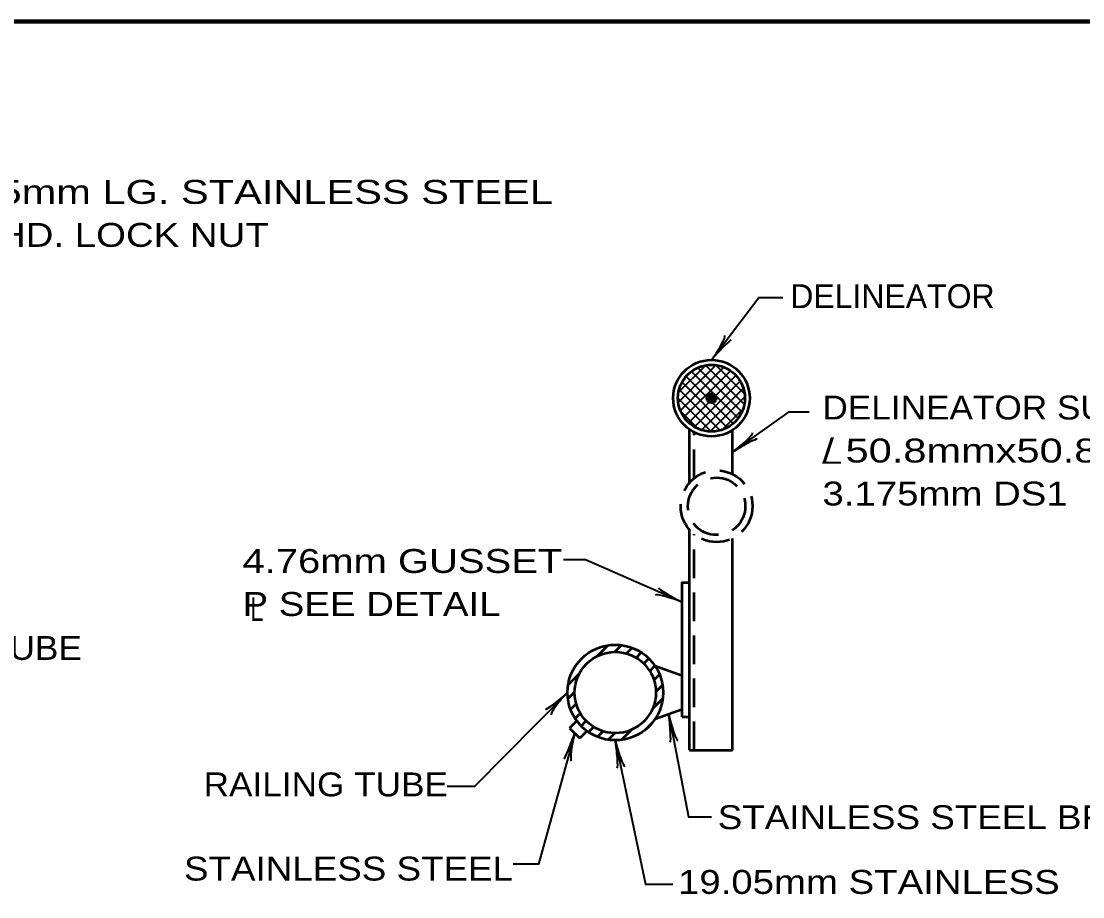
# Model space of a CAD drawing. Extents: x -105 to 751, y -65 to 479.
# Drawn here: x 308.2 to 441.4, y 362.8 to 472.7 of the extents above; entities that cross this region are included whole.
import ezdxf

# ---------------------------------------------------------------- set-up
doc = ezdxf.new("R2010")
doc.units = 0
doc.header["$LTSCALE"] = 1.2
doc.linetypes.add('MEDIUM_DASHED', pattern=[4.5, 3, -1.5])
doc.layers.add('1', color=7, linetype='Continuous', lineweight=35)

msp = doc.modelspace()

# ---------------------------------------------------------------- hatches: boundary and pattern name
at = {"layer": '1'}
msp.add_hatch(color=256, dxfattribs=at).paths.add_polyline_path([(395.414, 425.376, 1), (394.214, 425.376, 1)])

# ---------------------------------------------------------------- linework, layer by layer
for p, q in [((390.651, 424.82), (395.369, 429.538)), ((390.691, 426.134), (394.056, 429.498)), ((390.918, 423.815), (396.375, 429.272)), ((398.641, 423.662), (393.099, 429.203)), ((398.939, 424.636), (394.074, 429.502)), ((398.981, 425.867), (395.305, 429.543)), ((391.367, 422.991), (397.199, 428.823)), ((397.553, 422.204), (391.642, 428.115)), ((391.956, 422.307), (397.882, 428.233)), ((398.172, 422.858), (392.296, 428.734)), ((397.839, 428.282), (397.719, 428.402)), ((395.894, 421.318), (390.755, 426.456)), ((396.801, 421.683), (391.121, 427.364)), ((392.682, 421.76), (398.429, 427.508)), ((393.567, 421.373), (398.816, 426.622)), ((394.759, 421.18), (390.617, 425.322)), ((394.654, 421.186), (399.003, 425.536)), ((393.135, 421.531), (390.967, 423.699)), ((396.14, 421.4), (398.789, 424.049)), ((408.763, 417.317), (411.028, 417.317))]:
    msp.add_line(p, q, dxfattribs=at)
at = {"layer": '1', "lineweight": 53}
for p, q in [((392.049, 414.74), (392.049, 421.452)), ((397.449, 415.837), (397.449, 421.364)), ((392.049, 381.186), (392.049, 408.863)), ((397.449, 381.186), (397.449, 407.767)), ((380.414, 392.949), (381.798, 394.333)), ((382.669, 393.507), (383.52, 394.358)), ((384.166, 393.306), (384.876, 394.017)), ((385.349, 392.793), (386.007, 393.451)), ((386.311, 392.058), (386.946, 392.693)), ((387.071, 391.12), (387.716, 391.766)), ((387.751, 391.752), (391.149, 390.552)), ((376.837, 389.371), (378.236, 390.771)), ((387.603, 389.955), (388.311, 390.664)), ((387.843, 388.499), (388.672, 389.327)), ((376.805, 387.643), (377.657, 388.495)), ((387.408, 386.366), (388.687, 387.646)), ((377.15, 386.29), (377.854, 386.994)), ((391.149, 386.286), (387.751, 385.086)), ((377.721, 385.165), (378.372, 385.816)), ((391.149, 385.386), (392.049, 385.386)), ((377.87, 384.813), (377.021, 383.964)), ((377.021, 383.964), (378.294, 382.692)), ((378.469, 384.216), (379.113, 384.86)), ((379.403, 383.453), (380.052, 384.102)), ((383.52, 382.478), (384.807, 383.765)), ((386.453, 383.715), (387.456, 384.717)), ((379.142, 383.54), (378.294, 382.692)), ((380.509, 382.862), (381.209, 383.562)), ((381.835, 382.491), (382.673, 383.328)), ((392.049, 381.186), (397.449, 381.186))]:
    msp.add_line(p, q, dxfattribs=at)
at = {"layer": '1', "linetype": 'MEDIUM_DASHED', "lineweight": 53}
for p, q in [((392.649, 415.318), (392.649, 421.092)), ((392.649, 381.186), (392.649, 408.285))]:
    msp.add_line(p, q, dxfattribs=at)
at = {"layer": '1', "lineweight": 158}
msp.add_lwpolyline([(744.128, 472.7), (-47.572, 472.6), (-47.472, -53.4)], dxfattribs=at)
at = {"layer": '1'}
for points in [[(394.814, 430.176), (400.753, 437.999), (403.781, 437.999)], [(397.449, 418.6), (404.571, 423.643), (407.073, 423.643)], [(391.149, 399.745), (379.029, 405.073), (376.264, 405.073)], [(376.749, 388.419), (365.073, 376.626), (361.65, 376.626)], [(389.45, 385.686), (391.932, 372.806), (394.829, 372.806)], [(377.657, 383.328), (373.105, 366.88), (369.945, 366.88)], [(382.749, 382.419), (386.534, 364.377), (389.957, 364.377)]]:
    msp.add_lwpolyline(points, dxfattribs=at)
at = {"layer": '1', "lineweight": 53}
msp.add_lwpolyline([(391.149, 385.386), (391.149, 402.252), (392.049, 402.252)], dxfattribs=at)
for centre, radius in [((394.814, 425.376), 4.8), ((394.814, 425.376), 4.2), ((394.814, 425.376), 0.6), ((382.749, 388.419), 6), ((382.749, 388.419), 5.1)]:
    msp.add_circle(centre, radius, dxfattribs=at)
at = {"layer": '1', "linetype": 'MEDIUM_DASHED', "lineweight": 53}
for radius in [4.5, 3.6]:
    msp.add_circle((395.456, 411.802), radius, dxfattribs=at)
at = {"layer": '1', "lineweight": 40}
for centre, major_axis, ratio, start_param, end_param in [((395.341, 431.419), (-1.147, -1.82), 0.122415, 0.8963533, 3.1415927), ((395.341, 431.419), (-1.147, -1.82), 0.122415, 0.8963533, 3.1415927), ((395.829, 431.093), (1.442, 1.551), 0.07063, 6.2823074, 8.5597026), ((395.829, 431.093), (1.442, 1.551), 0.07063, 6.2823074, 8.5597026), ((398.326, 419.627), (-1.641, -1.391), 0.122415, 0.8963533, 3.1415927), ((398.326, 419.627), (-1.641, -1.391), 0.122415, 0.8963533, 3.1415927), ((398.693, 419.17), (-1.842, -1.046), 0.07063, 3.1407148, 5.41811), ((398.693, 419.17), (-1.842, -1.046), 0.07063, 3.1407148, 5.41811), ((390.02, 400.518), (1.845, -1.041), 0.07063, 3.1407148, 5.41811), ((390.02, 400.518), (1.845, -1.041), 0.07063, 3.1407148, 5.41811), ((389.816, 399.968), (2.037, -0.691), 0.122415, 0.8963533, 3.1415927), ((389.816, 399.968), (2.037, -0.691), 0.122415, 0.8963533, 3.1415927), ((375.622, 387.642), (1.633, 1.35), 0.07063, 3.1407148, 5.41811), ((375.622, 387.642), (1.633, 1.35), 0.07063, 3.1407148, 5.41811), ((376.063, 387.255), (1.374, 1.655), 0.122415, 0.8963533, 3.1415927), ((376.063, 387.255), (1.374, 1.655), 0.122415, 0.8963533, 3.1415927), ((389.455, 384.318), (-0.192, 2.11), 0.07063, 3.1407148, 5.41811), ((389.455, 384.318), (-0.192, 2.11), 0.07063, 3.1407148, 5.41811), ((390.023, 384.463), (-0.589, 2.069), 0.122415, 0.8963533, 3.1415927), ((390.023, 384.463), (-0.589, 2.069), 0.122415, 0.8963533, 3.1415927), ((377.054, 382.1), (-0.765, -1.975), 0.07063, 6.2823074, 8.5597026), ((377.054, 382.1), (-0.765, -1.975), 0.07063, 6.2823074, 8.5597026), ((377.628, 381.977), (0.391, 2.115), 0.122415, 0.8963533, 3.1415927), ((377.628, 381.977), (0.391, 2.115), 0.122415, 0.8963533, 3.1415927), ((382.776, 381.051), (-0.227, 2.106), 0.07063, 3.1407148, 5.41811), ((382.776, 381.051), (-0.227, 2.106), 0.07063, 3.1407148, 5.41811), ((383.342, 381.206), (-0.623, 2.059), 0.122415, 0.8963533, 3.1415927), ((383.342, 381.206), (-0.623, 2.059), 0.122415, 0.8963533, 3.1415927)]:
    msp.add_ellipse(centre, major_axis=major_axis, ratio=ratio, start_param=start_param, end_param=end_param, dxfattribs=at)

# ---------------------------------------------------------------- texts
at = {"layer": '1'}
for s, width, p in [('7.94mm 0 x 19.05mm LG. STAINLESS STEEL', 1.3, (266.524, 449.773)), ('BOLT WITH HEX HD. LOCK NUT', 1.2, (266.524, 444.373)), ('DELINEATOR SUPPORT', 1.1, (408.739, 422.699)), ('/ 50.8mmx50.8mmx', 1.3, (408.739, 417.299)), ('3.175mm DS1', 1.2, (408.739, 411.899)), ('4.76mm GUSSET', 1.25, (335.976, 403.434)), ('P SEE DETAIL', 1.2, (335.976, 398.034)), ('L', 0.75, (336.948, 397.384)), ('RAILING TUBE', 1.1, (285.173, 392.519)), ('RAILING TUBE', 1.1, (331.106, 375.385)), ('STAINLESS STEEL BRACKET', 1.15, (395.605, 371.27)), ('STAINLESS STEEL', 1.15, (328.638, 364.814)), ('19.05mm STAINLESS', 1.2, (390.617, 363.139))]:
    msp.add_text(s, height=3, dxfattribs=dict(at, width=width)).set_placement(p)
msp.add_text('DELINEATOR', height=3, dxfattribs=at).set_placement((404.703, 436.682))

doc.saveas('drawing.dxf')
